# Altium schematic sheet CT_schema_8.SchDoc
size 274 x 160 mm
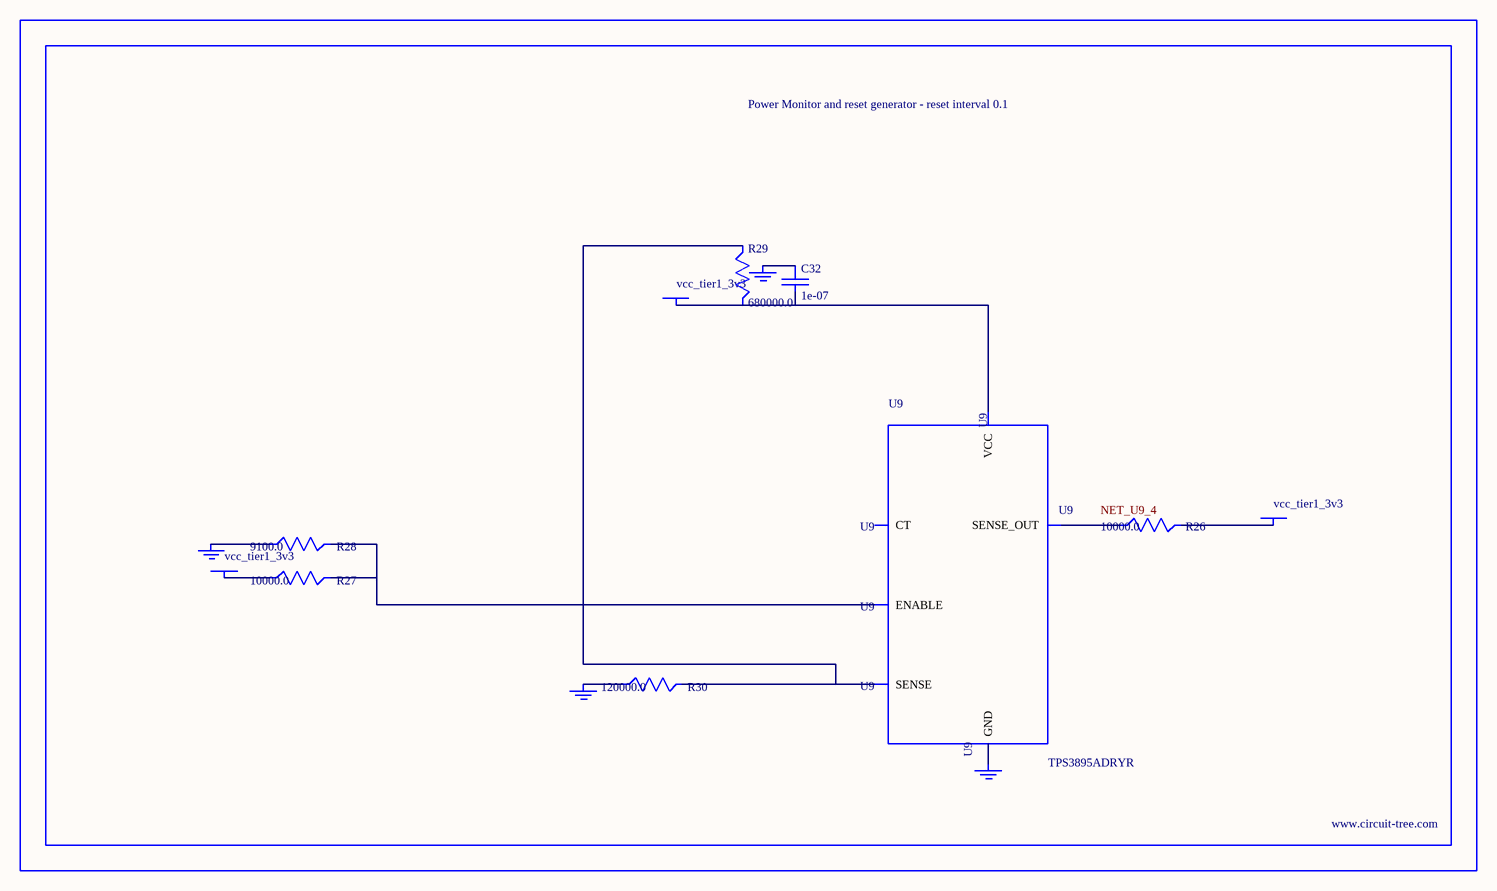
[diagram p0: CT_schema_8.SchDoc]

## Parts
BORDER7  (no value)
C32  1e-07  [C0402]
GND_INSTANCE_7_0  (no value)
GND_INSTANCE_7_1  (no value)
GND_INSTANCE_7_2  (no value)
GND_INSTANCE_7_3  (no value)
POWER_INSTANCE_7_0  vcc_tier1_3v3
POWER_INSTANCE_7_1  vcc_tier1_3v3
POWER_INSTANCE_7_2  vcc_tier1_3v3
R26  10000.0  [R0603]
R27  10000.0  [R0603]
R28  9100.0  [R0603]
R29  680000.0  [R0603]
R30  120000.0  [R0603]
U9  TPS3895ADRYR  [SON-6]

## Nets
NetC32_1: C32.1 GND_INSTANCE_7_2.0(GND)
NetC32_2: C32.2 POWER_INSTANCE_7_2.0(PWR) R29.2 U9.6(VCC)
NetGND_INSTANCE_7_0_0: GND_INSTANCE_7_0.0(GND) R28.1
NetGND_INSTANCE_7_1_0: GND_INSTANCE_7_1.0(GND) R30.1
NetGND_INSTANCE_7_3_0: GND_INSTANCE_7_3.0(GND) U9.2(GND)
NetPOWER_INSTANCE_7_0_0: POWER_INSTANCE_7_0.0(PWR) R27.1
NetPOWER_INSTANCE_7_1_0: POWER_INSTANCE_7_1.0(PWR) R26.2
NetR26_1: R26.1 U9.4(SENSE_OUT)
NetR27_2: R27.2 R28.2 U9.1(ENABLE)
NetR29_1: R29.1 R30.2 U9.3(SENSE)

Not connected (* = marked no-connect by the designer): U9 5(CT)

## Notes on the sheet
- Labels drawn without touching a wire or pin: NET_U9_4

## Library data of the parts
BORDER7 = BORDER_PAGE7
C32 = C0402C104K3RACTU
GND_INSTANCE_7_0-GND_INSTANCE_7_3 = GND
POWER_INSTANCE_7_0-POWER_INSTANCE_7_2 = PWR
R26 R27 = RC0603JR-0710KL
R28 = RC0603JR-079K1L
R29 = RC0603JR-07680KL
R30 = RC0603JR-07120KL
